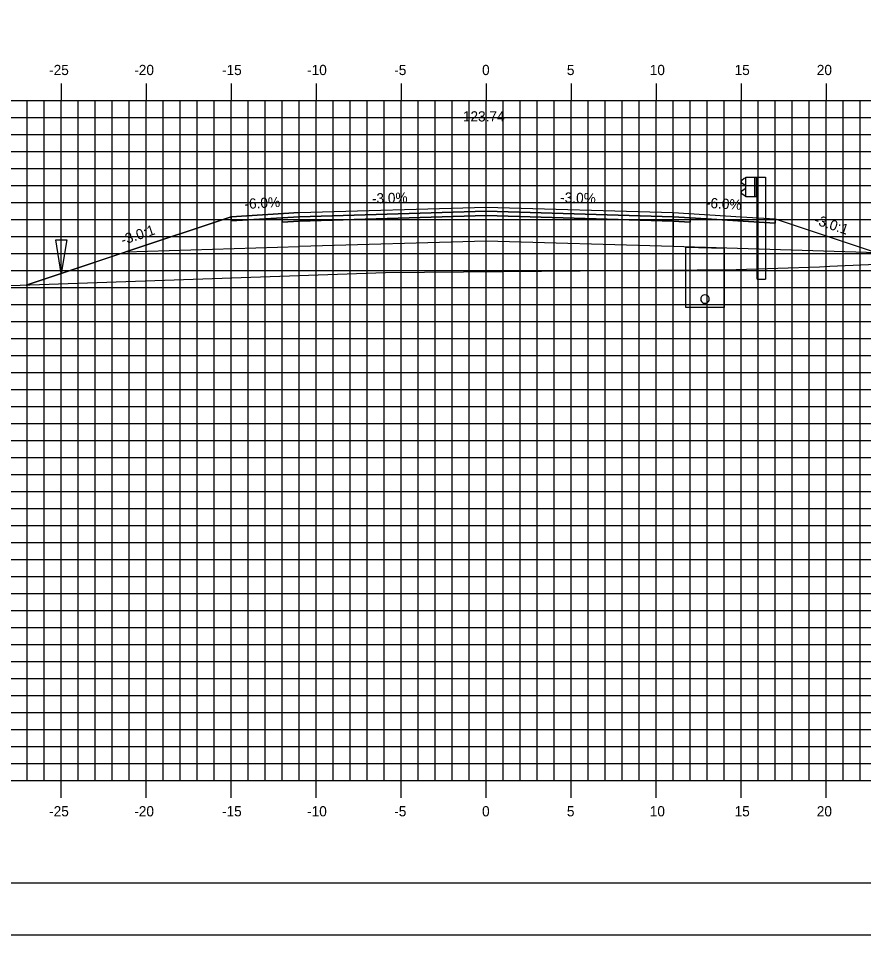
# Model space of a CAD drawing. Extents: x 850598 to 870284, y 366541 to 366651.
# Drawn here: x 854393.2 to 854443, y 366541.2 to 366595.1 of the extents above; entities that cross this region are included whole.
import ezdxf

# ---------------------------------------------------------------- set-up
doc = ezdxf.new("R2010")
doc.units = 0
for name, color, linetype in [('ANNOTATION', 7, 'Continuous'), ('BORDER', 7, 'Continuous'), ('D_Drainage_Ditch_Line', 7, 'Continuous'), ('D_Drainage_Underdrain', 7, 'Continuous'), ('D_Drainage_Underdrain_06in', 7, 'Continuous'), ('D_Guardrail_Beam_Rt', 7, 'Continuous'), ('D_Roadway_Centerline', 7, 'Continuous'), ('D_Roadway_Centerline_Text', 7, 'Continuous'), ('D_Roadway_Edge_Shoulder', 7, 'Continuous'), ('D_Roadway_Edge_TW', 7, 'Continuous'), ('D_Roadway_Pavement', 7, 'Continuous'), ('D_Roadway_SlopeLines', 7, 'Continuous'), ('D_Roadway_SubGrade', 7, 'Continuous'), ('H_V ANNOTATION', 7, 'Continuous'), ('MAJOR', 7, 'Continuous'), ('MINOR', 7, 'Continuous'), ('PLOT BOUNDARY', 7, 'Continuous'), ('S_Roadway_Centerline', 7, 'Continuous')]:
    doc.layers.add(name, color=color, linetype=linetype)

msp = doc.modelspace()

# ---------------------------------------------------------------- linework, layer by layer
at = {"layer": 'BORDER'}
msp.add_line((854375.758, 366544.225), (854535.758, 366544.225), dxfattribs=at)
at = {"layer": 'D_Drainage_Ditch_Line'}
msp.add_lwpolyline([(854395.43, 366582.029), (854396.086, 366582.029), (854395.758, 366580.06)], close=True, dxfattribs=at)
at = {"layer": 'D_Drainage_Underdrain'}
msp.add_lwpolyline([(854434.758, 366581.551), (854434.758, 366578.051), (854432.508, 366578.051), (854432.508, 366581.596)], close=True, dxfattribs=at)
at = {"layer": 'D_Drainage_Underdrain_06in'}
msp.add_lwpolyline([(854433.633, 366578.801), (854433.556, 366578.789), (854433.486, 366578.753), (854433.431, 366578.698), (854433.395, 366578.628), (854433.383, 366578.551), (854433.395, 366578.474), (854433.431, 366578.404), (854433.486, 366578.349), (854433.556, 366578.313), (854433.633, 366578.301), (854433.71, 366578.313), (854433.78, 366578.349), (854433.835, 366578.404), (854433.871, 366578.474), (854433.883, 366578.551), (854433.871, 366578.628), (854433.835, 366578.698), (854433.78, 366578.753), (854433.71, 366578.789)], close=True, dxfattribs=at)
at = {"layer": 'D_Guardrail_Beam_Rt'}
for p, q in [((854435.939, 366585.633), (854435.796, 366585.533)), ((854436.029, 366585.652), (854435.956, 366585.639)), ((854436.029, 366585.727), (854436.717, 366585.727)), ((854436.029, 366584.56), (854436.029, 366585.727)), ((854436.55, 366585.727), (854436.55, 366584.56)), ((854436.654, 366585.727), (854436.654, 366584.56)), ((854436.717, 366585.727), (854437.187, 366585.727)), ((854436.717, 366585.727), (854436.717, 366584.56)), ((854437.187, 366585.727), (854437.187, 366579.727)), ((854435.796, 366585.39), (854435.991, 366585.253)), ((854436.025, 366585.189), (854436.025, 366585.098)), ((854435.991, 366585.034), (854435.796, 366584.897)), ((854435.796, 366584.754), (854435.939, 366584.654)), ((854435.956, 366584.647), (854436.029, 366584.635)), ((854436.717, 366584.56), (854436.029, 366584.56)), ((854436.696, 366579.727), (854436.696, 366584.56)), ((854436.696, 366579.727), (854437.187, 366579.727))]:
    msp.add_line(p, q, dxfattribs=at)
for centre, major_axis, start_param, end_param in [((854435.963, 366585.599), (-0.0417, 0), 4.886922, 5.323254), ((854435.846, 366585.461), (-0.0877, 0), 5.323254, 7.243116), ((854435.946, 366585.189), (0.0789, 0), 0, 0.959931), ((854435.946, 366585.098), (0.0789, 0), 5.323254, 6.283185), ((854435.846, 366584.826), (-0.0877, 0), 5.323254, 7.243116), ((854435.963, 366584.688), (-0.0417, 0), 0.959931, 1.396263)]:
    msp.add_ellipse(centre, major_axis=major_axis, ratio=0.995501, start_param=start_param, end_param=end_param, dxfattribs=at)
at = {"layer": 'D_Roadway_Centerline'}
msp.add_lwpolyline([(854393.694, 366579.372), (854395.758, 366580.06), (854399.56, 366581.327), (854405.758, 366583.393), (854409.758, 366583.633), (854420.758, 366583.963), (854431.758, 366583.633), (854435.758, 366583.393), (854437.758, 366583.273), (854443.758, 366581.273), (854490.552, 366568.225), (854502.208, 366564.975), (854512.07, 366562.225), (854516.07, 366562.225)], dxfattribs=at)
at = {"layer": 'D_Roadway_Edge_Shoulder'}
for points in [[(854409.758, 366583.633), (854405.758, 366583.393), (854405.758, 366583.143), (854408.758, 366583.323), (854409.758, 366583.383)], [(854431.758, 366583.633), (854435.758, 366583.393), (854435.758, 366583.393), (854437.758, 366583.273), (854437.758, 366583.023), (854432.758, 366583.323), (854431.758, 366583.383)]]:
    msp.add_lwpolyline(points, close=True, dxfattribs=at)
at = {"layer": 'D_Roadway_Edge_TW'}
msp.add_lwpolyline([(854409.758, 366583.383), (854409.758, 366583.633), (854420.758, 366583.963), (854431.758, 366583.633), (854431.758, 366583.383), (854420.758, 366583.713)], close=True, dxfattribs=at)
at = {"layer": 'D_Roadway_Pavement'}
for points in [[(854409.758, 366583.133), (854409.758, 366583.383), (854420.758, 366583.713), (854431.758, 366583.383), (854431.758, 366583.133), (854420.758, 366583.463)], [(854409.758, 366583.383), (854408.758, 366583.323), (854408.758, 366583.073), (854409.758, 366583.133)], [(854431.758, 366583.383), (854432.758, 366583.323), (854432.758, 366583.073), (854431.758, 366583.133)]]:
    msp.add_lwpolyline(points, close=True, dxfattribs=at)
at = {"layer": 'D_Roadway_SlopeLines'}
for points in [[(854409.758, 366583.633), (854405.758, 366583.393), (854395.758, 366580.06)], [(854395.758, 366580.06), (854393.694, 366579.372)]]:
    msp.add_lwpolyline(points, dxfattribs=at)
at = {"layer": 'D_Roadway_SubGrade'}
for points in [[(854409.758, 366583.133), (854408.758, 366583.073), (854408.758, 366583.323), (854405.758, 366583.143), (854405.758, 366583.393), (854399.56, 366581.327), (854409.758, 366581.633)], [(854409.758, 366581.633), (854409.758, 366583.133), (854420.758, 366583.463), (854431.758, 366583.133), (854431.758, 366581.633), (854420.758, 366581.963)], [(854431.758, 366583.133), (854432.758, 366583.073), (854432.758, 366583.323), (854437.758, 366583.023), (854437.758, 366583.273), (854443.758, 366581.273), (854431.758, 366581.633)]]:
    msp.add_lwpolyline(points, close=True, dxfattribs=at)
at = {"layer": 'MAJOR'}
for p, q in [((854395.758, 366591.227), (854395.758, 366590.225)), ((854395.758, 366591.227), (854395.758, 366590.225)), ((854400.758, 366591.227), (854400.758, 366590.225)), ((854400.758, 366591.227), (854400.758, 366590.225)), ((854405.758, 366591.227), (854405.758, 366590.225)), ((854405.758, 366591.227), (854405.758, 366590.225)), ((854410.758, 366591.227), (854410.758, 366590.225)), ((854410.758, 366591.227), (854410.758, 366590.225)), ((854415.758, 366591.227), (854415.758, 366590.225)), ((854415.758, 366591.227), (854415.758, 366590.225)), ((854420.758, 366591.227), (854420.758, 366590.225)), ((854420.758, 366591.227), (854420.758, 366590.225)), ((854425.758, 366591.227), (854425.758, 366590.225)), ((854425.758, 366591.227), (854425.758, 366590.225)), ((854430.758, 366591.227), (854430.758, 366590.225)), ((854430.758, 366591.227), (854430.758, 366590.225)), ((854435.758, 366591.227), (854435.758, 366590.225)), ((854435.758, 366591.227), (854435.758, 366590.225)), ((854440.758, 366591.227), (854440.758, 366590.225)), ((854440.758, 366591.227), (854440.758, 366590.225)), ((854380.758, 366590.225), (854520.758, 366590.225)), ((854380.758, 366590.225), (854520.758, 366590.225)), ((854380.758, 366590.225), (854520.758, 366590.225)), ((854380.758, 366590.225), (854520.758, 366590.225)), ((854395.758, 366550.225), (854395.758, 366590.225)), ((854395.758, 366550.225), (854395.758, 366590.225)), ((854400.758, 366550.225), (854400.758, 366590.225)), ((854400.758, 366550.225), (854400.758, 366590.225)), ((854405.758, 366550.225), (854405.758, 366590.225)), ((854405.758, 366550.225), (854405.758, 366590.225)), ((854410.758, 366550.225), (854410.758, 366590.225)), ((854410.758, 366550.225), (854410.758, 366590.225)), ((854415.758, 366550.225), (854415.758, 366590.225)), ((854415.758, 366550.225), (854415.758, 366590.225)), ((854420.758, 366550.225), (854420.758, 366590.225)), ((854420.758, 366550.225), (854420.758, 366590.225)), ((854425.758, 366550.225), (854425.758, 366590.225)), ((854425.758, 366550.225), (854425.758, 366590.225)), ((854430.758, 366550.225), (854430.758, 366590.225)), ((854430.758, 366550.225), (854430.758, 366590.225)), ((854435.758, 366550.225), (854435.758, 366590.225)), ((854435.758, 366550.225), (854435.758, 366590.225)), ((854440.758, 366550.225), (854440.758, 366590.225)), ((854440.758, 366550.225), (854440.758, 366590.225)), ((854380.758, 366585.225), (854520.758, 366585.225)), ((854380.758, 366585.225), (854520.758, 366585.225)), ((854380.758, 366580.225), (854520.758, 366580.225)), ((854380.758, 366580.225), (854520.758, 366580.225)), ((854380.758, 366575.225), (854520.758, 366575.225)), ((854380.758, 366575.225), (854520.758, 366575.225)), ((854380.758, 366570.225), (854520.758, 366570.225)), ((854380.758, 366570.225), (854520.758, 366570.225)), ((854380.758, 366565.225), (854520.758, 366565.225)), ((854380.758, 366565.225), (854520.758, 366565.225)), ((854380.758, 366560.225), (854520.758, 366560.225)), ((854380.758, 366560.225), (854520.758, 366560.225)), ((854380.758, 366555.225), (854520.758, 366555.225)), ((854380.758, 366555.225), (854520.758, 366555.225)), ((854380.758, 366550.225), (854520.758, 366550.225)), ((854380.758, 366550.225), (854520.758, 366550.225)), ((854380.758, 366550.225), (854520.758, 366550.225)), ((854380.758, 366550.225), (854520.758, 366550.225)), ((854395.758, 366549.223), (854395.758, 366550.225)), ((854395.758, 366549.223), (854395.758, 366550.225)), ((854400.758, 366549.223), (854400.758, 366550.225)), ((854400.758, 366549.223), (854400.758, 366550.225)), ((854405.758, 366549.223), (854405.758, 366550.225)), ((854405.758, 366549.223), (854405.758, 366550.225)), ((854410.758, 366549.223), (854410.758, 366550.225)), ((854410.758, 366549.223), (854410.758, 366550.225)), ((854415.758, 366549.223), (854415.758, 366550.225)), ((854415.758, 366549.223), (854415.758, 366550.225)), ((854420.758, 366549.223), (854420.758, 366550.225)), ((854420.758, 366549.223), (854420.758, 366550.225)), ((854425.758, 366549.223), (854425.758, 366550.225)), ((854425.758, 366549.223), (854425.758, 366550.225)), ((854430.758, 366549.223), (854430.758, 366550.225)), ((854430.758, 366549.223), (854430.758, 366550.225)), ((854435.758, 366549.223), (854435.758, 366550.225)), ((854435.758, 366549.223), (854435.758, 366550.225)), ((854440.758, 366549.223), (854440.758, 366550.225)), ((854440.758, 366549.223), (854440.758, 366550.225))]:
    msp.add_line(p, q, dxfattribs=at)
at = {"layer": 'MINOR'}
for p, q in [((854393.758, 366550.225), (854393.758, 366590.225)), ((854393.758, 366550.225), (854393.758, 366590.225)), ((854394.758, 366550.225), (854394.758, 366590.225)), ((854394.758, 366550.225), (854394.758, 366590.225)), ((854396.758, 366550.225), (854396.758, 366590.225)), ((854396.758, 366550.225), (854396.758, 366590.225)), ((854397.758, 366550.225), (854397.758, 366590.225)), ((854397.758, 366550.225), (854397.758, 366590.225)), ((854398.758, 366550.225), (854398.758, 366590.225)), ((854398.758, 366550.225), (854398.758, 366590.225)), ((854399.758, 366550.225), (854399.758, 366590.225)), ((854399.758, 366550.225), (854399.758, 366590.225)), ((854401.758, 366550.225), (854401.758, 366590.225)), ((854401.758, 366550.225), (854401.758, 366590.225)), ((854402.758, 366550.225), (854402.758, 366590.225)), ((854402.758, 366550.225), (854402.758, 366590.225)), ((854403.758, 366550.225), (854403.758, 366590.225)), ((854403.758, 366550.225), (854403.758, 366590.225)), ((854404.758, 366550.225), (854404.758, 366590.225)), ((854404.758, 366550.225), (854404.758, 366590.225)), ((854406.758, 366550.225), (854406.758, 366590.225)), ((854406.758, 366550.225), (854406.758, 366590.225)), ((854407.758, 366550.225), (854407.758, 366590.225)), ((854407.758, 366550.225), (854407.758, 366590.225)), ((854408.758, 366550.225), (854408.758, 366590.225)), ((854408.758, 366550.225), (854408.758, 366590.225)), ((854409.758, 366550.225), (854409.758, 366590.225)), ((854409.758, 366550.225), (854409.758, 366590.225)), ((854411.758, 366550.225), (854411.758, 366590.225)), ((854411.758, 366550.225), (854411.758, 366590.225)), ((854412.758, 366550.225), (854412.758, 366590.225)), ((854412.758, 366550.225), (854412.758, 366590.225)), ((854413.758, 366550.225), (854413.758, 366590.225)), ((854413.758, 366550.225), (854413.758, 366590.225)), ((854414.758, 366550.225), (854414.758, 366590.225)), ((854414.758, 366550.225), (854414.758, 366590.225)), ((854416.758, 366550.225), (854416.758, 366590.225)), ((854416.758, 366550.225), (854416.758, 366590.225)), ((854417.758, 366550.225), (854417.758, 366590.225)), ((854417.758, 366550.225), (854417.758, 366590.225)), ((854418.758, 366550.225), (854418.758, 366590.225)), ((854418.758, 366550.225), (854418.758, 366590.225)), ((854419.758, 366550.225), (854419.758, 366590.225)), ((854419.758, 366550.225), (854419.758, 366590.225)), ((854421.758, 366550.225), (854421.758, 366590.225)), ((854421.758, 366550.225), (854421.758, 366590.225)), ((854422.758, 366550.225), (854422.758, 366590.225)), ((854422.758, 366550.225), (854422.758, 366590.225)), ((854423.758, 366550.225), (854423.758, 366590.225)), ((854423.758, 366550.225), (854423.758, 366590.225)), ((854424.758, 366550.225), (854424.758, 366590.225)), ((854424.758, 366550.225), (854424.758, 366590.225)), ((854426.758, 366550.225), (854426.758, 366590.225)), ((854426.758, 366550.225), (854426.758, 366590.225)), ((854427.758, 366550.225), (854427.758, 366590.225)), ((854427.758, 366550.225), (854427.758, 366590.225)), ((854428.758, 366550.225), (854428.758, 366590.225)), ((854428.758, 366550.225), (854428.758, 366590.225)), ((854429.758, 366550.225), (854429.758, 366590.225)), ((854429.758, 366550.225), (854429.758, 366590.225)), ((854431.758, 366550.225), (854431.758, 366590.225)), ((854431.758, 366550.225), (854431.758, 366590.225)), ((854432.758, 366550.225), (854432.758, 366590.225)), ((854432.758, 366550.225), (854432.758, 366590.225)), ((854433.758, 366550.225), (854433.758, 366590.225)), ((854433.758, 366550.225), (854433.758, 366590.225)), ((854434.758, 366550.225), (854434.758, 366590.225)), ((854434.758, 366550.225), (854434.758, 366590.225)), ((854436.758, 366550.225), (854436.758, 366590.225)), ((854436.758, 366550.225), (854436.758, 366590.225)), ((854437.758, 366550.225), (854437.758, 366590.225)), ((854437.758, 366550.225), (854437.758, 366590.225)), ((854438.758, 366550.225), (854438.758, 366590.225)), ((854438.758, 366550.225), (854438.758, 366590.225)), ((854439.758, 366550.225), (854439.758, 366590.225)), ((854439.758, 366550.225), (854439.758, 366590.225)), ((854441.758, 366550.225), (854441.758, 366590.225)), ((854441.758, 366550.225), (854441.758, 366590.225)), ((854442.758, 366550.225), (854442.758, 366590.225)), ((854442.758, 366550.225), (854442.758, 366590.225)), ((854380.758, 366589.225), (854520.758, 366589.225)), ((854380.758, 366589.225), (854520.758, 366589.225)), ((854380.758, 366588.225), (854520.758, 366588.225)), ((854380.758, 366588.225), (854520.758, 366588.225)), ((854380.758, 366587.225), (854520.758, 366587.225)), ((854380.758, 366587.225), (854520.758, 366587.225)), ((854380.758, 366586.225), (854520.758, 366586.225)), ((854380.758, 366586.225), (854520.758, 366586.225)), ((854380.758, 366584.225), (854520.758, 366584.225)), ((854380.758, 366584.225), (854520.758, 366584.225)), ((854380.758, 366583.225), (854520.758, 366583.225)), ((854380.758, 366583.225), (854520.758, 366583.225)), ((854380.758, 366582.225), (854520.758, 366582.225)), ((854380.758, 366582.225), (854520.758, 366582.225)), ((854380.758, 366581.225), (854520.758, 366581.225)), ((854380.758, 366581.225), (854520.758, 366581.225)), ((854380.758, 366579.225), (854520.758, 366579.225)), ((854380.758, 366579.225), (854520.758, 366579.225)), ((854380.758, 366578.225), (854520.758, 366578.225)), ((854380.758, 366578.225), (854520.758, 366578.225)), ((854380.758, 366577.225), (854520.758, 366577.225)), ((854380.758, 366577.225), (854520.758, 366577.225)), ((854380.758, 366576.225), (854520.758, 366576.225)), ((854380.758, 366576.225), (854520.758, 366576.225)), ((854380.758, 366574.225), (854520.758, 366574.225)), ((854380.758, 366574.225), (854520.758, 366574.225)), ((854380.758, 366573.225), (854520.758, 366573.225)), ((854380.758, 366573.225), (854520.758, 366573.225)), ((854380.758, 366572.225), (854520.758, 366572.225)), ((854380.758, 366572.225), (854520.758, 366572.225)), ((854380.758, 366571.225), (854520.758, 366571.225)), ((854380.758, 366571.225), (854520.758, 366571.225)), ((854380.758, 366569.225), (854520.758, 366569.225)), ((854380.758, 366569.225), (854520.758, 366569.225)), ((854380.758, 366568.225), (854520.758, 366568.225)), ((854380.758, 366568.225), (854520.758, 366568.225)), ((854380.758, 366567.225), (854520.758, 366567.225)), ((854380.758, 366567.225), (854520.758, 366567.225)), ((854380.758, 366566.225), (854520.758, 366566.225)), ((854380.758, 366566.225), (854520.758, 366566.225)), ((854380.758, 366564.225), (854520.758, 366564.225)), ((854380.758, 366564.225), (854520.758, 366564.225)), ((854380.758, 366563.225), (854520.758, 366563.225)), ((854380.758, 366563.225), (854520.758, 366563.225)), ((854380.758, 366562.225), (854520.758, 366562.225)), ((854380.758, 366562.225), (854520.758, 366562.225)), ((854380.758, 366561.225), (854520.758, 366561.225)), ((854380.758, 366561.225), (854520.758, 366561.225)), ((854380.758, 366559.225), (854520.758, 366559.225)), ((854380.758, 366559.225), (854520.758, 366559.225)), ((854380.758, 366558.225), (854520.758, 366558.225)), ((854380.758, 366558.225), (854520.758, 366558.225)), ((854380.758, 366557.225), (854520.758, 366557.225)), ((854380.758, 366557.225), (854520.758, 366557.225)), ((854380.758, 366556.225), (854520.758, 366556.225)), ((854380.758, 366556.225), (854520.758, 366556.225)), ((854380.758, 366554.225), (854520.758, 366554.225)), ((854380.758, 366554.225), (854520.758, 366554.225)), ((854380.758, 366553.225), (854520.758, 366553.225)), ((854380.758, 366553.225), (854520.758, 366553.225)), ((854380.758, 366552.225), (854520.758, 366552.225)), ((854380.758, 366552.225), (854520.758, 366552.225)), ((854380.758, 366551.225), (854520.758, 366551.225)), ((854380.758, 366551.225), (854520.758, 366551.225))]:
    msp.add_line(p, q, dxfattribs=at)
at = {"layer": 'PLOT BOUNDARY'}
msp.add_lwpolyline([(854367.665, 366541.166), (854537.665, 366541.166), (854537.665, 366651.166), (854367.665, 366651.166)], close=True, dxfattribs=at)
at = {"layer": 'S_Roadway_Centerline'}
msp.add_lwpolyline([(854380.758, 366579.024), (854382.313, 366579.015), (854386.529, 366579.124), (854414.842, 366580.106), (854435.467, 366580.28), (854440.368, 366580.438), (854440.98, 366580.486), (854445.083, 366580.658), (854446.418, 366580.573), (854448.399, 366581.104), (854451.486, 366582.031), (854452.45, 366582.336), (854453.513, 366582.694), (854462.157, 366583.084), (854468.461, 366583.332), (854476.624, 366583.005), (854482.323, 366582.689), (854483.12, 366582.712), (854484.412, 366582.636), (854486.59, 366581.935), (854487.826, 366581.607), (854500.471, 366572.526), (854508.957, 366566.366), (854520.758, 366559.496)], dxfattribs=at)

# ---------------------------------------------------------------- texts
at = {"layer": 'ANNOTATION'}
for s, rotation, p in [('-6.0%', 3.4336, (854406.555, 366583.843)), ('-3.0%', 1.7184, (854414.046, 366584.163)), ('-3.0%', 358.2816, (854425.106, 366584.233)), ('-6.0%', 356.5664, (854433.675, 366583.92)), ('-3.0:1', 341.5651, (854440.012, 366582.976)), ('-3.0:1', 18.4348, (854399.38, 366581.721))]:
    msp.add_text(s, height=0.6, rotation=rotation, dxfattribs=at).set_placement(p)
at = {"layer": 'D_Roadway_Centerline'}
for s, p in [('C', (854420.753, 366583.963)), ('C', (854420.753, 366583.963)), ('L', (854420.758, 366583.956)), ('L', (854420.758, 366583.956))]:
    msp.add_text(s, height=0.0146, dxfattribs=at).set_placement(p)
at = {"layer": 'D_Roadway_Centerline_Text'}
msp.add_text('123.74', height=0.6, dxfattribs=at).set_placement((854419.388, 366588.995))
at = {"layer": 'H_V ANNOTATION'}
for s, p in [('-25', (854395.044, 366591.725)), ('-20', (854400.052, 366591.725)), ('-15', (854405.215, 366591.725)), ('-10', (854410.223, 366591.725)), ('-5', (854415.349, 366591.725)), ('0', (854420.517, 366591.725)), ('5', (854425.509, 366591.725)), ('10', (854430.384, 366591.725)), ('15', (854435.376, 366591.725)), ('20', (854440.212, 366591.725)), ('-25', (854395.044, 366548.125)), ('-20', (854400.052, 366548.125)), ('-15', (854405.215, 366548.125)), ('-10', (854410.223, 366548.125)), ('-5', (854415.349, 366548.125)), ('0', (854420.517, 366548.125)), ('5', (854425.509, 366548.125)), ('10', (854430.384, 366548.125)), ('15', (854435.376, 366548.125)), ('20', (854440.212, 366548.125))]:
    msp.add_text(s, height=0.6, dxfattribs=at).set_placement(p)

doc.saveas('drawing.dxf')
